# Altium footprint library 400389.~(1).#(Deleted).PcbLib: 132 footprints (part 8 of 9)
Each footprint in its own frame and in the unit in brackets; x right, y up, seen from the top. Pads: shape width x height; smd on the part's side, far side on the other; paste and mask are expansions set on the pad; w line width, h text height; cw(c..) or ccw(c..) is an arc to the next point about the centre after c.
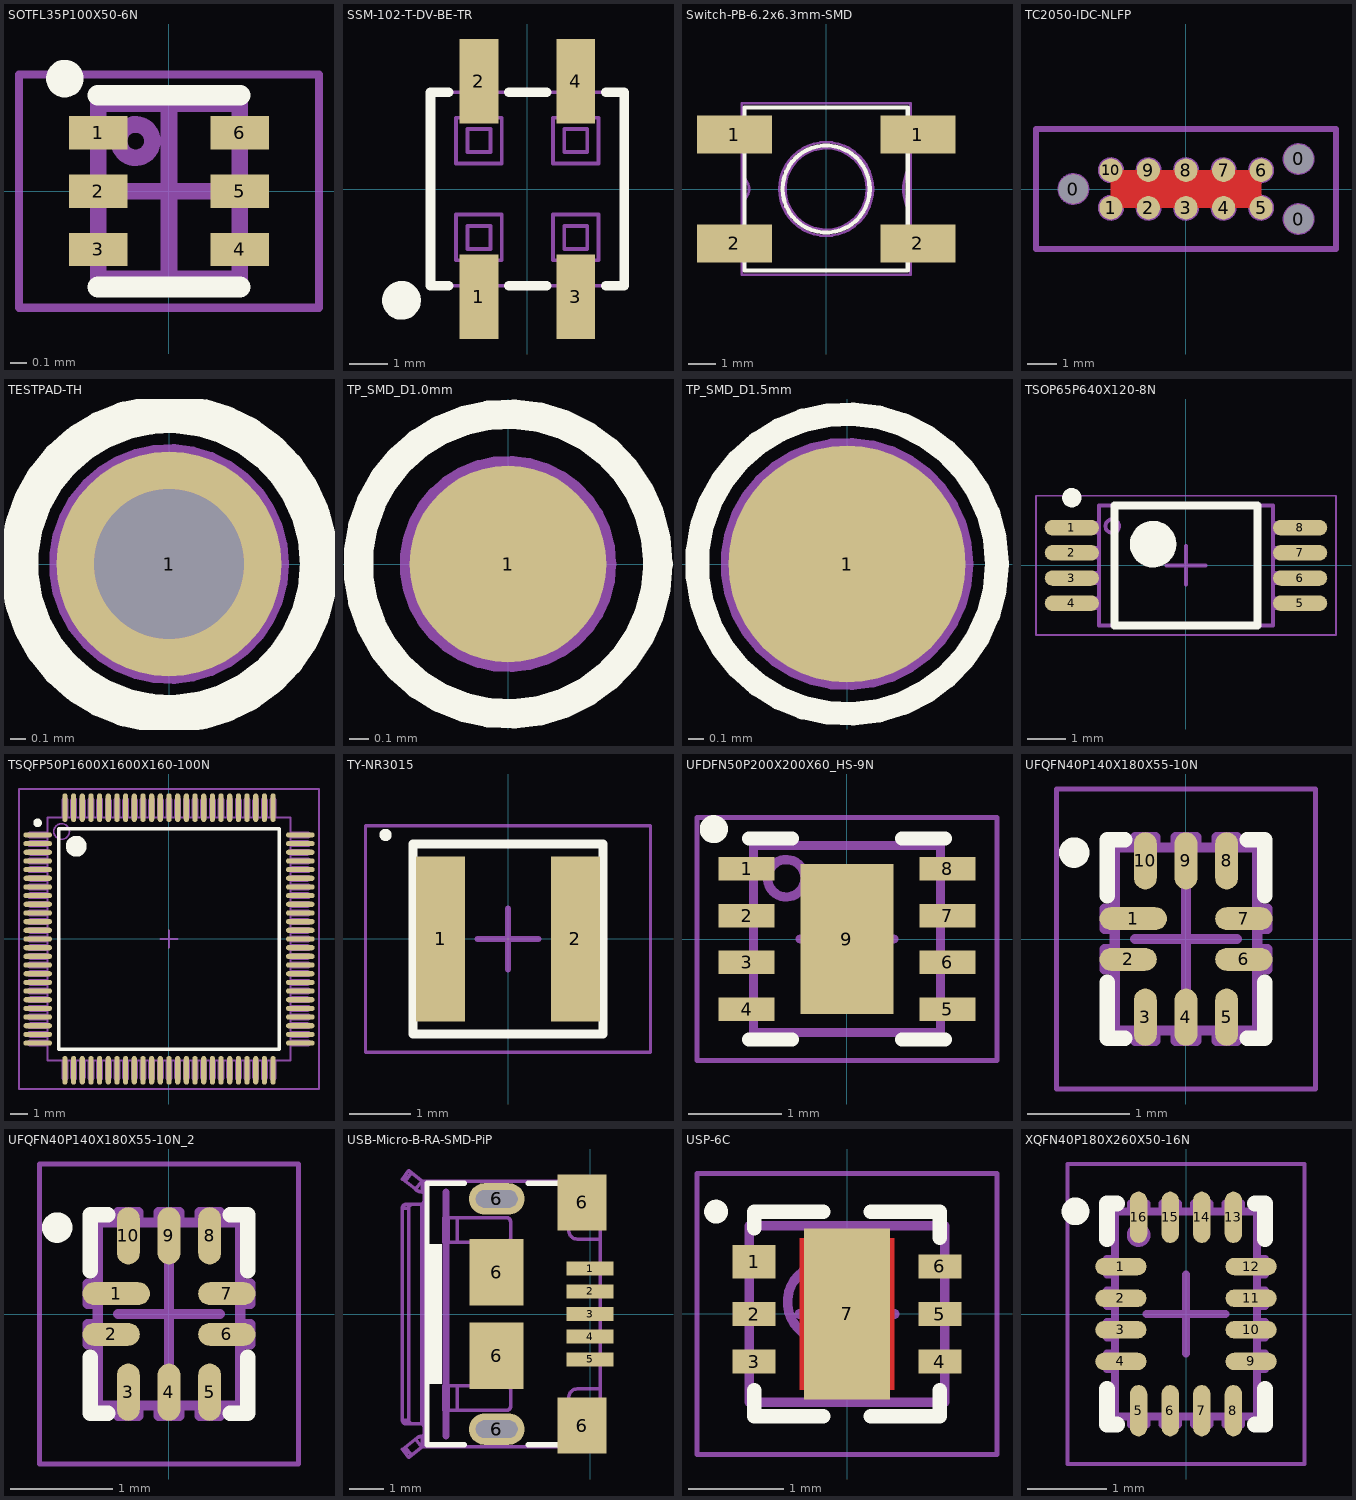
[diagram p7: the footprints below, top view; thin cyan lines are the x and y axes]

## SOTFL35P100X50-6N [mm]
pads (6):
  rect 0.35x0.2 smd mask+0.05: 1(-0.425,0.35) 2(-0.425,0) 3(-0.425,-0.35) 4(0.425,-0.35) 5(0.425,0) 6(0.425,0.35)
Top Overlay:
  circle w0.125: c-0.625,0.675 r0.05
  lines w0.125: -0.425,-0.575 0.425,-0.575 ; -0.425,0.575 0.425,0.575
Mechanical 7:
  circle w0.1: c-0.2,0.3 r0.1
  lines w0.1: -0.425,-0.525 -0.425,0.525 0.425,0.525 0.425,-0.525 -0.425,-0.525
  text ".Designator" at 0.325,-0.4 h0.3
Mechanical 15:
  lines w0.05: -0.9,-0.7 0.9,-0.7 0.9,0.7 -0.9,0.7 -0.9,-0.7
  lines w0.1: -0.5,0 0.5,0 ; 0,-0.5 0,0.5
3D body "SOTFL35P100X50-6N.step": height 0.5, standoff 0, extent -0.5,-0.523 0.5,0.523

## SSM-102-T-DV-BE-TR [mm]
pads (4):
  rect 1.02x2.22 smd: 1(-1.27,-2.825) 2(-1.27,2.825) 3(1.27,-2.825) 4(1.27,2.825)
Top Overlay:
  circle w0.508: c-3.302,-2.921 r0.254
  lines w0.254: -2.06,-2.54 -2.54,-2.54 -2.54,2.54 -2.06,2.54 ; -0.49,-2.54 0.5,-2.54 ; -0.49,2.54 0.5,2.54 ; 2.06,-2.54 2.54,-2.54 2.54,2.54 2.06,2.54
Mechanical 7:
  lines w0.1: -1.62,-2.54 -1.62,-3.082 ccw(c-1.27,-3.082) -0.92,-3.082 -0.92,-2.54 ; -1.62,2.54 -1.62,3.082 cw(c-1.27,3.082) -0.92,3.082 -0.92,2.54 ; 0.92,-2.54 0.92,-3.082 ccw(c1.27,-3.082) 1.62,-3.082 1.62,-2.54 ; 0.92,2.54 0.92,3.082 cw(c1.27,3.082) 1.62,3.082 1.62,2.54 ; -2.54,-2.54 -2.54,2.54 2.54,2.54 2.54,-2.54 -2.54,-2.54 ; -1.87,-1.87 -1.87,-0.67 -0.67,-0.67 -0.67,-1.87 -1.87,-1.87 ; -1.87,0.67 -0.67,0.67 -0.67,1.87 -1.87,1.87 -1.87,0.67 ; -1.57,-1.57 -1.57,-0.97 -0.97,-0.97 -0.97,-1.57 -1.57,-1.57 ; -1.57,0.97 -0.97,0.97 -0.97,1.57 -1.57,1.57 -1.57,0.97 ; 0.67,-1.87 0.67,-0.67 1.87,-0.67 1.87,-1.87 0.67,-1.87 ; 0.67,0.67 1.87,0.67 1.87,1.87 0.67,1.87 0.67,0.67 ; 0.97,-1.57 0.97,-0.97 1.57,-0.97 1.57,-1.57 0.97,-1.57 ; 0.97,0.97 1.57,0.97 1.57,1.57 0.97,1.57 0.97,0.97
  text ".Designator" at -1.829,-0.127 h0.38
3D body "SSM-102-T-DV-BE-TR.stp": height 7.47, standoff 0.05, extent -2.54,-3.518 2.54,3.518

## Switch-PB-6.2x6.3mm-SMD [mm]
pads (4):
  rect 2.75x1.4 smd: 1(-3.375,2) 1(3.375,2) 2(-3.375,-2) 2(3.375,-2)
Top Overlay:
  circle w0.152: c0,0 r1.601
  lines w0.152: -3,-3 3,-3 3,3 -3,3 -3,-3
Mechanical 7:
  circle w0.1: c0,0 r1.5
  circle w0.1: c0,0 r1.721
  lines w0.1: -3.3,-2.393 -3.3,-1.606 ; -3.3,1.606 -3.3,2.393 ; -3.1,-2.393 -3.6,-2.393 -3.6,-1.606 -3.1,-1.606 ; -3.1,-0.441 ccw(c-3.335,0) -3.1,0.441 ; -3.1,1.606 -3.6,1.606 -3.6,2.393 -3.1,2.393 ; 3.1,-2.393 3.6,-2.393 3.6,-1.606 3.1,-1.606 ; 3.1,-0.91 cw(c4.561,0) 3.1,0.91 ; 3.1,1.606 3.6,1.606 3.6,2.393 3.1,2.393 ; 3.3,-2.393 3.3,-1.606 ; 3.3,1.606 3.3,2.393 ; -3.1,-3.15 3.1,-3.15 3.1,3.15 -3.1,3.15 -3.1,-3.15
  text ".Designator" at -0.475,-0.15 h0.38
3D body "Switch tact 6x6mm.stp": height 3.1, standoff 0, extent -4,-3 4,3.3

## TC2050-IDC-NLFP [mil]
pads (13):
  round 39 hole 39 unplated mask+3: 0(-150,0) 0(150,-40) 0(150,40)
  round 31 smd paste-196.85: 1(-100,-25) 2(-50,-25) 3(0,-25) 4(50,-25) 5(100,-25) 6(100,25) 7(50,25) 8(0,25) 9(-50,25) 10(-100,25)
Top Layer:
  pour cut-out: -100,25 -100,-25 100,-25 100,25
Mechanical 7:
  circle w3.94: c-150,0 r19.26
  circle w3.94: c150,39.98 r19.26
  circle w3.94: c150,-39.98 r19.26
  circle w3.94: c100,24.99 r15.45
  circle w3.94: c100,-24.99 r15.45
  circle w3.94: c50,-24.99 r15.45
  circle w3.94: c50,24.99 r15.45
  circle w3.94: c-50,24.99 r15.45
  circle w3.94: c0,24.99 r15.45
  circle w3.94: c0,-24.99 r15.45
  circle w3.94: c-50,-24.99 r15.45
  circle w3.94: c-100,-24.99 r15.45
  circle w3.94: c-100,24.99 r15.45
  text ".Designator" at -35.43,-64.96 h15
Mechanical 8:
  circle w3.94: c150,-39.98 r19.26
  circle w3.94: c150,39.98 r19.26
  circle w3.94: c-150,0 r19.26
Mechanical 15:
  lines w7.87: -199.8,-79.92 199.8,-79.92 199.8,79.92 -199.8,79.92 -199.8,-79.92

## TESTPAD-TH [mm]
pads (1):
  round 1.5 hole 1: 1(0,0)
Top Overlay:
  circle w0.254: c0,0 r1
Mechanical 7:
  circle w0.1: c0,0 r1
  circle w0.1: c0,0 r0.75
  circle w0.1: c0,0 r0.5
  text ".Designator" at -0.5,1.15 h0.38

## TP_SMD_D1.0mm [mm]
pads (1):
  round 1 smd paste-5: 1(0,0)
Top Overlay:
  circle w0.15: c0,0 r0.762
Mechanical 7:
  circle w0.1: c0,0 r0.762
  circle w0.1: c0,0 r0.5
  text ".Designator" at -0.633,0.918 h0.38

## TP_SMD_D1.5mm [mm]
pads (1):
  round 1.5 smd paste-5: 1(0,0)
Top Overlay:
  circle w0.15: c0,0 r0.95
Mechanical 7:
  circle w0.1: c0,0 r0.75
  circle w0.1: c0,0 r0.95
  text ".Designator" at -0.9,1.175 h0.38
3D body: height 0.05, standoff 0, extent -0.75,-0.75 0.75,0.75

## TSOP65P640X120-8N [mm]
pads (8):
  oval 1.4x0.4 smd: 1(-2.95,0.975) 2(-2.95,0.325) 3(-2.95,-0.325) 4(-2.95,-0.975) 5(2.95,-0.975) 6(2.95,-0.325) 7(2.95,0.325) 8(2.95,0.975)
Top Overlay:
  circle w0.6: c-0.85,0.55 r0.3
  circle w0.25: c-2.95,1.75 r0.125
  lines w0.2: -1.85,-1.55 1.85,-1.55 1.85,1.55 -1.85,1.55 -1.85,-1.55
Mechanical 7:
  circle w0.1: c-1.905,1.016 r0.175
  lines w0.1: -2.25,-1.55 2.25,-1.55 2.25,1.55 -2.25,1.55 -2.25,-1.55
  lines w0.102: -2.25,-1.1 -3.25,-1.1 -3.25,-0.85 -2.25,-0.85 ; -2.25,-0.45 -3.25,-0.45 -3.25,-0.2 -2.25,-0.2 ; -2.25,0.2 -3.25,0.2 -3.25,0.45 -2.25,0.45 ; -2.25,0.85 -3.25,0.85 -3.25,1.1 -2.25,1.1 ; 2.25,-1.1 3.25,-1.1 3.25,-0.85 2.25,-0.85 ; 2.25,-0.45 3.25,-0.45 3.25,-0.2 2.25,-0.2 ; 2.25,0.2 3.25,0.2 3.25,0.45 2.25,0.45 ; 2.25,0.85 3.25,0.85 3.25,1.1 2.25,1.1
  text ".Designator" at -0.559,-0.178 h0.38
Mechanical 15:
  lines w0.05: -3.875,-1.8 3.875,-1.8 3.875,1.8 -3.875,1.8 -3.875,-1.8
  lines w0.1: -0.5,0 0.5,0 ; 0,-0.5 0,0.5
3D body "TSOP65P640X120-8N_asfdasdf.step": height 1.2, standoff 0, extent -3.2,-1.55 3.2,1.55

## TSQFP50P1600X1600X160-100N [mm]
pads (100):
  oval 1.65x0.3 smd mask+0.05: 1(-7.575,6) 2(-7.575,5.5) 3(-7.575,5) 4(-7.575,4.5) 5(-7.575,4) 6(-7.575,3.5) 7(-7.575,3) 8(-7.575,2.5) 9(-7.575,2) 10(-7.575,1.5) 11(-7.575,1) 12(-7.575,0.5) 13(-7.575,0) 14(-7.575,-0.5) 15(-7.575,-1) 16(-7.575,-1.5) 17(-7.575,-2) 18(-7.575,-2.5) 19(-7.575,-3) 20(-7.575,-3.5) 21(-7.575,-4) 22(-7.575,-4.5) 23(-7.575,-5) 24(-7.575,-5.5) 25(-7.575,-6) 51(7.575,-6) 52(7.575,-5.5) 53(7.575,-5) 54(7.575,-4.5) 55(7.575,-4) 56(7.575,-3.5) 57(7.575,-3) 58(7.575,-2.5) 59(7.575,-2) 60(7.575,-1.5) 61(7.575,-1) 62(7.575,-0.5) 63(7.575,0) 64(7.575,0.5) 65(7.575,1) 66(7.575,1.5) 67(7.575,2) 68(7.575,2.5) 69(7.575,3) 70(7.575,3.5) 71(7.575,4) 72(7.575,4.5) 73(7.575,5) 74(7.575,5.5) 75(7.575,6)
  oval 0.3x1.65 smd mask+0.05: 26(-6,-7.575) 27(-5.5,-7.575) 28(-5,-7.575) 29(-4.5,-7.575) 30(-4,-7.575) 31(-3.5,-7.575) 32(-3,-7.575) 33(-2.5,-7.575) 34(-2,-7.575) 35(-1.5,-7.575) 36(-1,-7.575) 37(-0.5,-7.575) 38(0,-7.575) 39(0.5,-7.575) 40(1,-7.575) 41(1.5,-7.575) 42(2,-7.575) 43(2.5,-7.575) 44(3,-7.575) 45(3.5,-7.575) 46(4,-7.575) 47(4.5,-7.575) 48(5,-7.575) 49(5.5,-7.575) 50(6,-7.575) 76(6,7.575) 77(5.5,7.575) 78(5,7.575) 79(4.5,7.575) 80(4,7.575) 81(3.5,7.575) 82(3,7.575) 83(2.5,7.575) 84(2,7.575) 85(1.5,7.575) 86(1,7.575) 87(0.5,7.575) 88(0,7.575) 89(-0.5,7.575) 90(-1,7.575) 91(-1.5,7.575) 92(-2,7.575) 93(-2.5,7.575) 94(-3,7.575) 95(-3.5,7.575) 96(-4,7.575) 97(-4.5,7.575) 98(-5,7.575) 99(-5.5,7.575) 100(-6,7.575)
Top Overlay:
  circle w0.25: c-7.575,6.7 r0.125
  circle w0.6: c-5.35,5.35 r0.3
  lines w0.2: -6.35,-6.35 -6.35,6.35 6.35,6.35 6.35,-6.35 -6.35,-6.35
Mechanical 7:
  drawing of 405 lines, arcs and shapes, not listed
Mechanical 15:
  lines w0.1: -0.5,0 0.5,0 ; 0,-0.5 0,0.5 ; -8.65,-8.65 -8.65,8.65 8.65,8.65 8.65,-8.65 -8.65,-8.65
3D body "User Library-LQFP-100 (2).step": height 1.6, standoff 0, extent -8.001,-8 7.999,8

## TY-NR3015 [mm]
pads (2):
  rect 0.8x2.7 smd: 1(-1.1,0) 2(1.1,0)
Top Overlay:
  circle w0.1: c-2,1.7 r0.05
  lines w0.15: -1.55,-1.55 -1.55,1.55 1.55,1.55 1.55,-1.55 -1.55,-1.55
Mechanical 7:
  lines w0.1: -1.55,-1.55 1.55,-1.55 1.55,1.55 -1.55,1.55 -1.55,-1.55
  text ".Designator" at -1.143,0 h0.38
Mechanical 13:
  lines w0.1: -1.55,-1.55 1.55,-1.55 1.55,1.55 -1.55,1.55 -1.55,-1.55
Mechanical 15:
  lines w0.05: -2.325,-1.85 -2.325,1.85 2.325,1.85 2.325,-1.85 -2.325,-1.85
  lines w0.1: -0.5,0 0.5,0 ; 0,-0.5 0,0.5
3D body "User Library-nr3015.step": height 1.35, standoff -0.15, extent -1.5,-1.5 1.5,1.5

## UFDFN50P200X200X60_HS-9N [mm]
pads (9):
  rect 0.6x0.25 smd: 1(-1.075,0.75) 2(-1.075,0.25) 3(-1.075,-0.25) 4(-1.075,-0.75) 5(1.075,-0.75) 6(1.075,-0.25) 7(1.075,0.25) 8(1.075,0.75)
  rect 1x1.6 smd: 9(0,0)
Top Overlay:
  circle w0.2: c-1.425,1.175 r0.05
  lines w0.15: -1.05,-1.075 -0.59,-1.075 ; -1.05,1.075 -0.59,1.075 ; 0.59,-1.075 1.05,-1.075 ; 0.59,1.075 1.05,1.075
Mechanical 7:
  circle w0.1: c-0.65,0.65 r0.2
  lines w0.1: -1,-1 1,-1 1,1 -1,1 -1,-1
Mechanical 15:
  lines w0.05: -1.605,-1.3 1.605,-1.3 1.605,1.3 -1.605,1.3 -1.605,-1.3
  lines w0.1: -0.5,0 0.5,0 ; 0,-0.5 0,0.5
3D body "SON50P200X60_HS-9N.step": height 0.6, standoff 0, extent -1.001,-1 1.001,1

## UFQFN40P140X180X55-10N [mm]
pads (10):
  oval 0.663x0.225 smd mask+0.055: 1(-0.519,0.2)
  oval 0.563x0.225 smd mask+0.055: 2(-0.569,-0.2) 6(0.569,-0.2) 7(0.569,0.2)
  oval 0.225x0.563 smd mask+0.055: 3(-0.4,-0.769) 4(0,-0.769) 5(0.4,-0.769) 8(0.4,0.769) 9(0,0.769) 10(-0.4,0.769)
Top Overlay:
  circle w0.2: c-1.1,0.85 r0.05
  lines w0.15: -0.775,-0.425 -0.775,-0.975 -0.6,-0.975 ; -0.775,0.425 -0.775,0.975 -0.6,0.975 ; 0.6,-0.975 0.775,-0.975 0.775,-0.425 ; 0.6,0.975 0.775,0.975 0.775,0.425
Mechanical 7:
  lines w0.1: -0.7,-0.3 -0.8,-0.3 -0.8,-0.1 -0.7,-0.1 ; -0.7,0.1 -0.8,0.1 -0.8,0.3 -0.7,0.3 ; -0.5,-0.9 -0.5,-1 -0.3,-1 -0.3,-0.9 ; -0.5,0.9 -0.5,1 -0.3,1 -0.3,0.9 ; -0.1,-0.9 -0.1,-1 0.1,-1 0.1,-0.9 ; -0.1,0.9 -0.1,1 0.1,1 0.1,0.9 ; 0.3,-0.9 0.3,-1 0.5,-1 0.5,-0.9 ; 0.3,0.9 0.3,1 0.5,1 0.5,0.9 ; 0.7,-0.3 0.8,-0.3 0.8,-0.1 0.7,-0.1 ; 0.7,0.1 0.8,0.1 0.8,0.3 0.7,0.3 ; -0.7,-0.9 0.7,-0.9 0.7,0.9 -0.7,0.9 -0.7,-0.9
  text ".Designator" at -0.45,-0.2 h0.38
Mechanical 15:
  lines w0.05: -1.275,-1.475 1.275,-1.475 1.275,1.475 -1.275,1.475 -1.275,-1.475
  lines w0.1: -0.5,0 0.5,0 ; 0,-0.5 0,0.5
3D body "QFN40P140X180X55-10N.step": height 0.55, standoff 0, extent -0.71,-0.91 0.71,0.91

## UFQFN40P140X180X55-10N_2 [mm]
pads (10):
  oval 0.663x0.225 smd mask+0.055: 1(-0.519,0.2)
  oval 0.563x0.225 smd mask+0.055: 2(-0.569,-0.2) 6(0.569,-0.2) 7(0.569,0.2)
  oval 0.225x0.563 smd mask+0.055: 3(-0.4,-0.769) 4(0,-0.769) 5(0.4,-0.769) 8(0.4,0.769) 9(0,0.769) 10(-0.4,0.769)
Top Overlay:
  circle w0.2: c-1.1,0.85 r0.05
  lines w0.15: -0.775,-0.425 -0.775,-0.975 -0.6,-0.975 ; -0.775,0.425 -0.775,0.975 -0.6,0.975 ; 0.6,-0.975 0.775,-0.975 0.775,-0.425 ; 0.6,0.975 0.775,0.975 0.775,0.425
Mechanical 7:
  lines w0.1: -0.7,-0.3 -0.8,-0.3 -0.8,-0.1 -0.7,-0.1 ; -0.7,0.1 -0.8,0.1 -0.8,0.3 -0.7,0.3 ; -0.5,-0.9 -0.5,-1 -0.3,-1 -0.3,-0.9 ; -0.5,0.9 -0.5,1 -0.3,1 -0.3,0.9 ; -0.1,-0.9 -0.1,-1 0.1,-1 0.1,-0.9 ; -0.1,0.9 -0.1,1 0.1,1 0.1,0.9 ; 0.3,-0.9 0.3,-1 0.5,-1 0.5,-0.9 ; 0.3,0.9 0.3,1 0.5,1 0.5,0.9 ; 0.7,-0.3 0.8,-0.3 0.8,-0.1 0.7,-0.1 ; 0.7,0.1 0.8,0.1 0.8,0.3 0.7,0.3 ; -0.7,-0.9 0.7,-0.9 0.7,0.9 -0.7,0.9 -0.7,-0.9
  text ".Designator" at -0.45,-0.2 h0.38
Mechanical 15:
  lines w0.05: -1.275,-1.475 1.275,-1.475 1.275,1.475 -1.275,1.475 -1.275,-1.475
  lines w0.1: -0.5,0 0.5,0 ; 0,-0.5 0,0.5
3D body "QFN40P140X180X55-10N.step": height 0.55, standoff 0, extent -0.71,-0.91 0.71,0.91

## USB-Micro-B-RA-SMD-PiP [mm]
pads (13):
  rect 1.35x0.4 smd: 1(0,1.3) 2(0,0.65) 3(0,0) 4(0,-0.65) 5(0,-1.3)
  oval 1.6x0.9 hole 0.5 slot 1.2 at 0 deg: 6(-2.675,-3.3) 6(-2.675,3.3)
  oval 2x1.5 on Top Paste: 6(-2.675,-3.3) 6(-2.675,3.3)
  rect 1.55x1.9 smd: 6(-2.675,-1.2) 6(-2.675,1.2)
  rect 1.4x1.6 smd: 6(-0.225,-3.2) 6(-0.225,3.2)
Top Overlay:
  rectangle: -4.75,-2 -4.25,2
  lines w0.152: -3.6,-3.75 -4.675,-3.75 -4.675,3.75 -3.6,3.75 ; -1.775,-3.75 0.25,-3.75 0.25,-3.275 ; -1.775,3.75 0.25,3.75 0.25,3.275
Mechanical 7:
  drawing of 2738 lines, arcs and shapes, not listed
  text ".Designator" at -4.125,-0.127 h0.38
Mechanical 15:
  lines w0.2: -4.125,-3.5 -4.125,3.5
3D body "User Library-MicroUSB-B_Molex_105017-0001.step": height 2.72, standoff -0.59, extent -5.28,-4.1 0.15,4.1

## USP-6C [mm]
pads (7):
  rect 0.45x0.35 smd paste-0.05: 1(-0.975,0.55)
  rect 0.45x0.25 smd paste-0.05: 2(-0.975,0) 3(-0.975,-0.5) 4(0.975,-0.5) 5(0.975,0) 6(0.975,0.5)
  rect 0.9x1.8 smd paste-2: 7(0,0)
Top Layer:
  rectangle: -0.5,-0.8 0.5,0.8
Top Overlay:
  circle w0.15: c-1.375,1.075 r0.05
  lines w0.15: -0.975,-0.8 -0.975,-1.075 -0.25,-1.075 ; -0.975,0.9 -0.975,1.075 -0.25,1.075 ; 0.25,-1.075 0.975,-1.075 0.975,-0.8 ; 0.25,1.075 0.975,1.075 0.975,0.8
Top Paste:
  rectangle: 0.8,0.375 1.15,0.625
  rectangle: 0.8,-0.125 1.15,0.125
  rectangle: 0.8,-0.625 1.15,-0.375
  rectangle: -1.15,-0.625 -0.8,-0.375
  rectangle: -1.15,-0.125 -0.8,0.125
  rectangle: -1.15,0.375 -0.8,0.725
  region: 0.4,-0.3 -0.4,-0.3 -0.4,-0.6 0.4,-0.6
  region: 0.25,-0.325 -0.25,-0.325 -0.25,-0.7 0.25,-0.7
  rectangle: -0.25,0.325 0.25,0.7
  rectangle: -0.4,0.3 0.4,0.6
Mechanical 7:
  circle w0.1: c-0.225,0.125 r0.4
  lines w0.1: -1.025,-0.925 1.025,-0.925 1.025,0.925 -1.025,0.925 -1.025,-0.925
  text ".Designator" at 0.125,-0.6 h0.38
Mechanical 15:
  lines w0.05: -1.575,-1.475 1.575,-1.475 1.575,1.475 -1.575,1.475 -1.575,-1.475
  lines w0.1: -0.5,0 0.5,0 ; 0,-0.5 0,0.5
3D body "QFN50P200X180X60_HS-7N.step": height 0.6, standoff 0, extent -0.926,-1.025 0.926,1.025

## XQFN40P180X260X50-16N [mm]
pads (16):
  oval 0.65x0.22 smd paste-0.02 mask+0.04: 1(-0.825,0.6) 2(-0.825,0.2) 3(-0.825,-0.2) 4(-0.825,-0.6) 9(0.825,-0.6) 10(0.825,-0.2) 11(0.825,0.2) 12(0.825,0.6)
  oval 0.22x0.65 smd paste-0.02 mask+0.04: 5(-0.6,-1.225) 6(-0.2,-1.225) 7(0.2,-1.225) 8(0.6,-1.225) 13(0.6,1.225) 14(0.2,1.225) 15(-0.2,1.225) 16(-0.6,1.225)
Top Overlay:
  circle w0.25: c-1.4,1.3 r0.05
  lines w0.2: -1,-0.95 -1,-1.4 -0.875,-1.4 ; -1,0.95 -1,1.4 -0.875,1.4 ; 0.875,-1.4 1,-1.4 1,-0.95 ; 0.875,1.4 1,1.4 1,0.95
Mechanical 7:
  circle w0.1: c-0.6,1 r0.1
  lines w0.1: -0.9,-0.7 -1,-0.7 -1,-0.5 -0.9,-0.5 ; -0.9,-0.3 -1,-0.3 -1,-0.1 -0.9,-0.1 ; -0.9,0.1 -1,0.1 -1,0.3 -0.9,0.3 ; -0.9,0.5 -1,0.5 -1,0.7 -0.9,0.7 ; -0.7,-1.3 -0.7,-1.4 -0.5,-1.4 -0.5,-1.3 ; -0.7,1.3 -0.7,1.4 -0.5,1.4 -0.5,1.3 ; -0.3,-1.3 -0.3,-1.4 -0.1,-1.4 -0.1,-1.3 ; -0.3,1.3 -0.3,1.4 -0.1,1.4 -0.1,1.3 ; 0.1,-1.3 0.1,-1.4 0.3,-1.4 0.3,-1.3 ; 0.1,1.3 0.1,1.4 0.3,1.4 0.3,1.3 ; 0.5,-1.3 0.5,-1.4 0.7,-1.4 0.7,-1.3 ; 0.5,1.3 0.5,1.4 0.7,1.4 0.7,1.3 ; 0.9,-0.7 1,-0.7 1,-0.5 0.9,-0.5 ; 0.9,-0.3 1,-0.3 1,-0.1 0.9,-0.1 ; 0.9,0.1 1,0.1 1,0.3 0.9,0.3 ; 0.9,0.5 1,0.5 1,0.7 0.9,0.7 ; -0.9,-1.3 0.9,-1.3 0.9,1.3 -0.9,1.3 -0.9,-1.3
  text ".Designator" at -0.45,-0.2 h0.38
Mechanical 15:
  lines w0.05: -1.5,-1.9 1.5,-1.9 1.5,1.9 -1.5,1.9 -1.5,-1.9
  lines w0.1: -0.5,0 0.5,0 ; 0,-0.5 0,0.5
3D body: height 0.55, standoff 0.4, extent -0.9,-0.35 0.9,0.35
3D body "User Library-XQFN-16-1.step": height 0.55, standoff 0, extent -0.91,-1.31 0.91,1.31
